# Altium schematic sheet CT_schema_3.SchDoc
size 278 x 277 mm
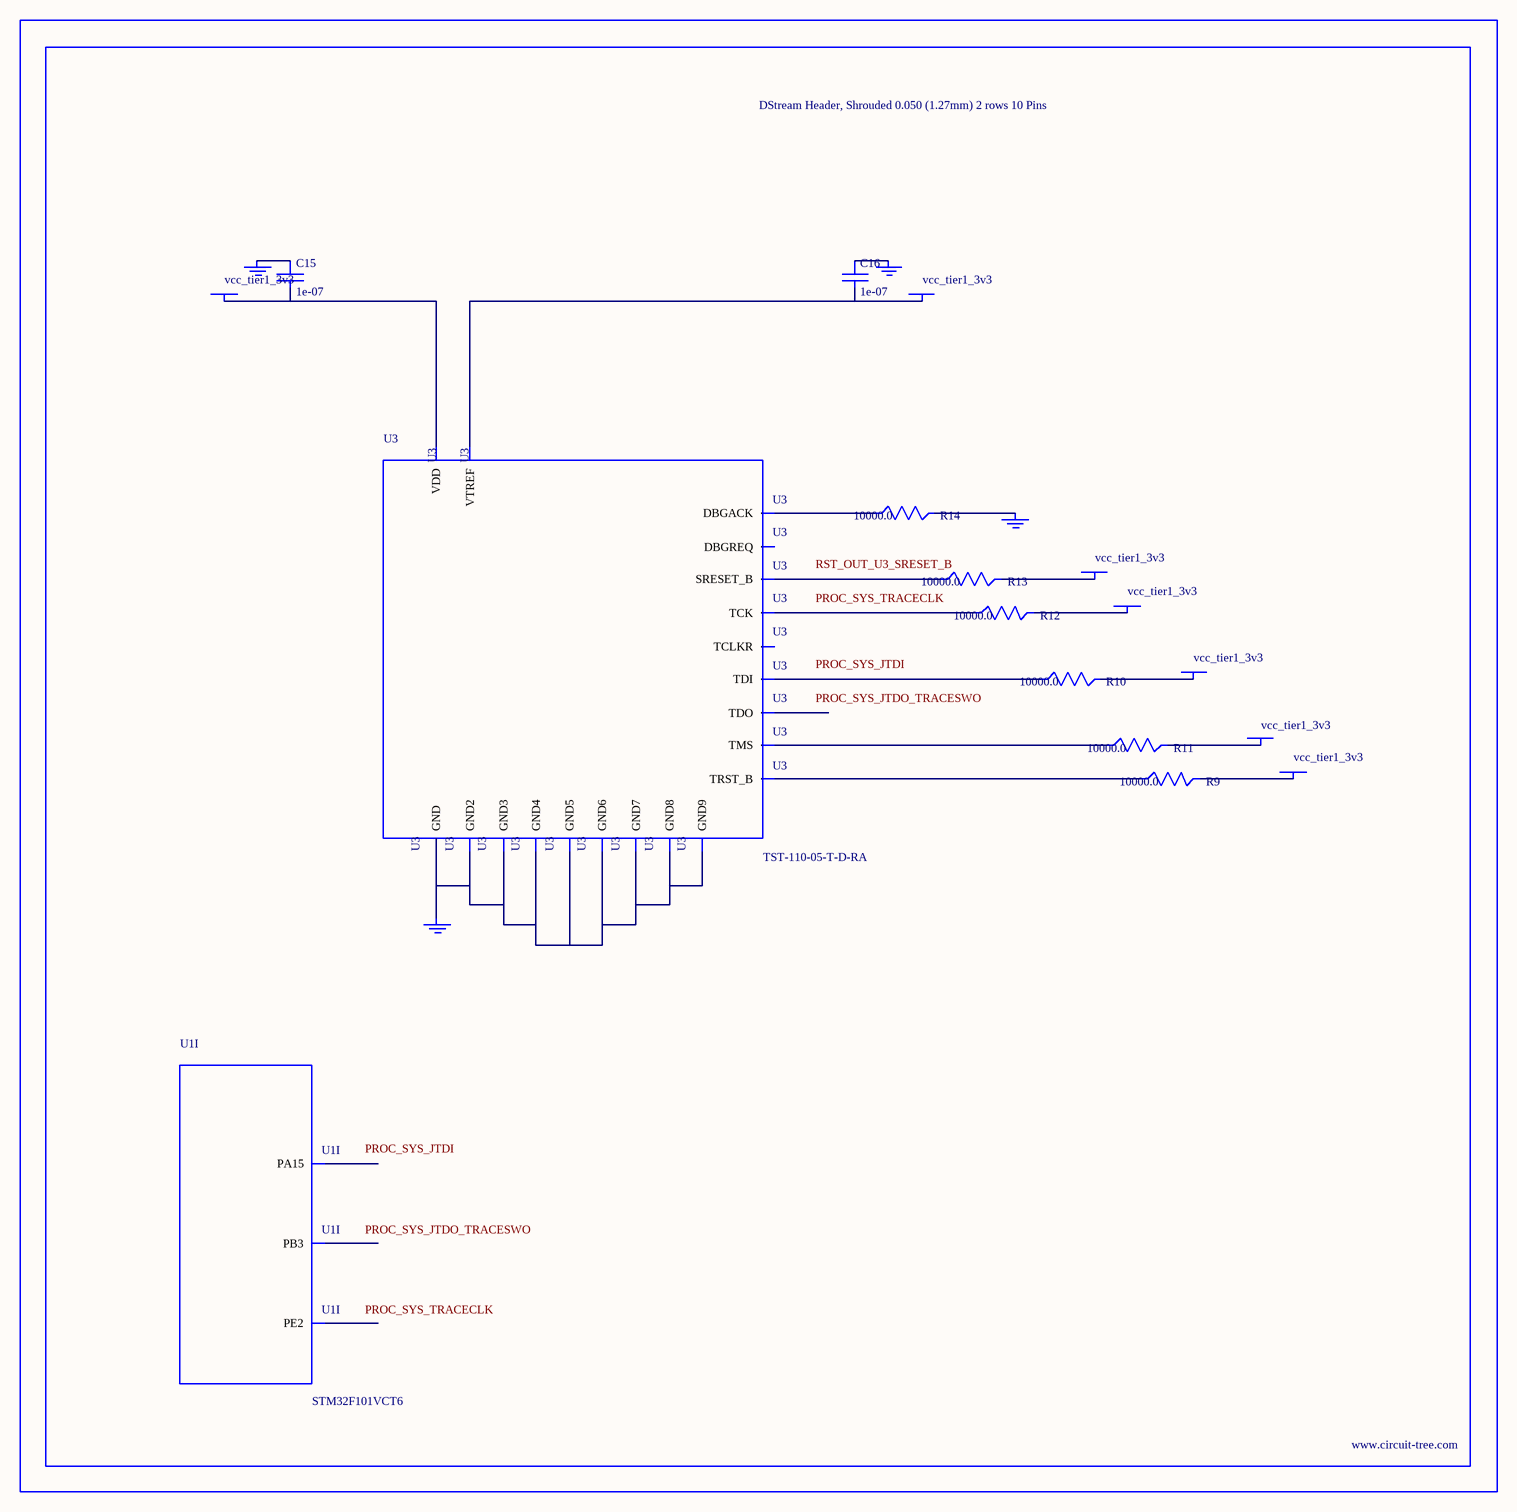
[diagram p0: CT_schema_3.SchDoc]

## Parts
BORDER2  (no value)
C15  1e-07  [C0402]
C16  1e-07  [C0402]
GND_INSTANCE_2_0  (no value)
GND_INSTANCE_2_1  (no value)
GND_INSTANCE_2_2  (no value)
GND_INSTANCE_2_3  (no value)
POWER_INSTANCE_2_0  vcc_tier1_3v3
POWER_INSTANCE_2_1  vcc_tier1_3v3
POWER_INSTANCE_2_2  vcc_tier1_3v3
POWER_INSTANCE_2_3  vcc_tier1_3v3
POWER_INSTANCE_2_4  vcc_tier1_3v3
POWER_INSTANCE_2_5  vcc_tier1_3v3
POWER_INSTANCE_2_6  vcc_tier1_3v3
R9  10000.0  [R0603]
R10  10000.0  [R0603]
R11  10000.0  [R0603]
R12  10000.0  [R0603]
R13  10000.0  [R0603]
R14  10000.0  [R0603]
U1  STM32F101VCT6  [LQFP100]  (part I of 9)
U3  TST-110-05-T-D-RA  [TST-110-05-T-D-RA]

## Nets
NetC15_1: C15.1 GND_INSTANCE_2_1.0(GND)
NetC15_2: C15.2 POWER_INSTANCE_2_1.0(PWR) U3.2(VDD)
NetC16_1: C16.1 GND_INSTANCE_2_0.0(GND)
NetC16_2: C16.2 POWER_INSTANCE_2_0.0(PWR) U3.1(VTREF)
NetGND_INSTANCE_2_2_0: GND_INSTANCE_2_2.0(GND) R14.2
NetGND_INSTANCE_2_3_0: GND_INSTANCE_2_3.0(GND) U3.4(GND) U3.6(GND2) U3.8(GND3) U3.10(GND4) U3.12(GND5) U3.14(GND6) U3.16(GND7) U3.18(GND8) U3.20(GND9)
NetPOWER_INSTANCE_2_2_0: POWER_INSTANCE_2_2.0(PWR) R9.2
NetPOWER_INSTANCE_2_3_0: POWER_INSTANCE_2_3.0(PWR) R10.2
NetPOWER_INSTANCE_2_4_0: POWER_INSTANCE_2_4.0(PWR) R11.2
NetPOWER_INSTANCE_2_5_0: POWER_INSTANCE_2_5.0(PWR) R12.2
NetPOWER_INSTANCE_2_6_0: POWER_INSTANCE_2_6.0(PWR) R13.2
NetR9_1: R9.1 U3.3(TRST_B)
NetR10_1: R10.1 U3.5(TDI)
NetR11_1: R11.1 U3.7(TMS)
NetR12_1: R12.1 U3.9(TCK)
NetR13_1: R13.1 U3.15(SRESET_B)
NetR14_1: R14.1 U3.19(DBGACK)

Not connected (* = marked no-connect by the designer): U1 1(PE2) 77(PA15) 89(PB3); U3 11(TCLKR) 13(TDO) 17(DBGREQ)

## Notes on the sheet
- Labels drawn without touching a wire or pin: PROC_SYS_JTDI, PROC_SYS_JTDO_TRACESWO, PROC_SYS_TRACECLK, RST_OUT_U3_SRESET_B

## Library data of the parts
BORDER2 = BORDER_PAGE2
C15 C16 = C0402C104K3RACTU
GND_INSTANCE_2_0-GND_INSTANCE_2_3 = GND
POWER_INSTANCE_2_0-POWER_INSTANCE_2_6 = PWR
R9-R14 = RC0603JR-0710KL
